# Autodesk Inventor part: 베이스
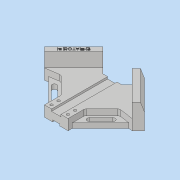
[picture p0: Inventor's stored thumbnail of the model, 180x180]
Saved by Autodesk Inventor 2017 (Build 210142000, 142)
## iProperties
Part Number: 베이스
Material: 일반
Document SubType Name: Modeling
Designer: 00-00
Density: 1 g/cm^3
Appearance: 기본값
Mass: 211.692 g
Surface Area: 407.229 cm^2
Volume: 211.692 cm^3
Author: 00-00
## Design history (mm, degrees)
sketch "스케치1"
  geometry: L1 (0, 84.853)-(84.853, 0); L2 (84.853, 0)-(0, -84.853); L3 (0, -84.853)-(-84.853, 0); L4 (-84.853, 0)-(0, 84.853); L5 (0, 84.853)-(0, -84.853); L6 (84.853, 0)-(-84.853, 0); L7 (0, 84.853)-(120, 84.853); 1 further point
  constraints: 14 end point, 2 midpoint, 2 parallel, 1 equal length, 1 horizontal, 1 perpendicular
  dimensions: "d0" = 120 distance of L1.start L1.end; "d1" = 45 deg angle of L1 L7; "d2" = 120 distance of L1.end L2.end
extrude "돌출1" new body sketch "스케치1" distance "d3" = 42; taper "d4" = 0 deg
sketch "스케치2"
  geometry: L1 (0, 84.853)-(-84.853, 0) reference; L2 (84.853, 0)-(0, 84.853) reference; L3 (-74.246, -10.607)-(0, 63.64); L4 (0, 63.64)-(74.246, -10.607); L5 (-84.853, 0)-(0, -84.853) reference; L6 (0, -84.853)-(84.853, 0) reference; L7 (-74.246, -10.607)-(0, -84.853); L8 (74.246, -10.607)-(0, -84.853); 1 further point
  constraints: 8 end point, 1 collinear, 1 perpendicular, 1 other
  dimensions: "d5" = 15 distance between parallel lines of L1 L3
extrude "돌출2" cut sketch "스케치2" distance "d6" = 24; taper "d7" = 0 deg
sketch "스케치3"
  geometry: L1 (-20, -64.853)-(20, -64.853); L2 (74.246, -10.607)-(0, -84.853) reference; L3 (0, -84.853)-(-74.246, -10.607) reference; 1 further point
  constraints: 2 end point, 2 point on line, 1 horizontal
  dimensions: "d8" = 20 distance from line of L2.end L1
extrude "돌출3" cut sketch "스케치3" stored distance "d9" = 24; taper "d10" = 0 deg
sketch "스케치4"
  geometry: L1 (-35.355, 49.497)-(-16.005, 30.147); L2 (16.005, 30.147)-(35.355, 49.497); L3 (84.853, 0)-(0, 84.853) reference; L4 (0, 84.853)-(-84.853, 0) reference; L5 (-16.005, 30.147)-(16.005, 30.147); L6 (-20, -64.853)-(20, -64.853) reference; 1 further point
  constraints: 6 end point, 2 parallel, 2 point on line, 1 horizontal
  dimensions: "d11" = 50 distance between parallel lines of L2 L4; "d12" = 50 distance between parallel lines of L3 L1; "d13" = 95 distance between parallel lines of L5 L6
extrude "돌출4" cut sketch "스케치4" stored distance "d14" = 24; taper "d15" = 0 deg
sketch "스케치5"
  geometry: L1 (-5, 42)-(0, 27); L2 (-15, 42)-(0, 42) reference; L3 (0, 0)-(0, 42) reference; 1 further point
  constraints: 2 end point, 2 point on line
  dimensions: "d16" = 5 distance from line of L3 L1.start; "d17" = 15 distance from line of L2 L1.end
extrude "돌출5" cut sketch "스케치5" stored distance "d18" = 24; taper "d19" = 0 deg
sketch "스케치6"
  geometry: L1 (-74.246, -10.607)-(-24.749, 38.891) reference; L2 (-74.246, -10.607)-(-49.497, -7.071); L3 (-49.497, -7.071)-(-20, -36.569); L4 (20, -64.853)-(-20, -64.853) reference; L5 (-20, -36.569)-(-20, -64.853); L6 (-20, -64.853)-(-74.246, -10.607) reference; L7 (-84.853, 0)-(-35.355, 49.497) reference; 1 further point
  constraints: 6 end point
  dimensions: "d20" = 20 distance between parallel lines of L6 L3; "d29" = 30 distance from line of L2.end L7; "d30" = 90 deg angle of L4 L5
extrude "돌출6" cut sketch "스케치6" distance "d21" = 10; taper "d22" = 0 deg
sketch "스케치7"
  geometry: L1 (-68.059, -9.723)-(-20, -57.782); L2 (-20, -64.853)-(-74.246, -10.607) reference; L3 (-74.246, -10.607)-(-49.497, -7.071) reference; L4 (-20, -36.569)-(-20, -64.853) reference; 1 further point
  constraints: 2 end point, 2 point on line, 1 parallel
  dimensions: "d23" = 5 distance between parallel lines of L2 L1
extrude "돌출7" cut sketch "스케치7" stored distance "d24" = 8; taper "d25" = 0 deg
sketch "스케치8"
  geometry: L1 (-49.497, -18.385)-(-29.698, -38.184); L2 (-52.326, -21.213)-(-32.527, -41.012); L3 (-26.87, -35.355)-(-46.669, -15.556); L4 (-68.059, -9.723)-(-20, -57.782) reference; L5 (-84.853, 0)-(-35.355, 49.497) reference; L6 (-81.317, -3.536)-(-74.246, -10.607) reference; A1 r 4 centre (-49.497, -18.385) between (-46.669, -15.556) and (-52.326, -21.213); A2 r 4 centre (-29.698, -38.184) between (-32.527, -41.012) and (-26.87, -35.355); 2 further points
  constraints: 8 end point, 4 point on circle, 4 tangent, 2 centre point, 2 parallel, 1 midpoint
  dimensions: "d27" = 4 radius of A2; "d28" = 38 distance from line of L1.start L5; "d31" = 12 distance from line of L6 point (-39.598, -28.284); "d32" = 28 distance of L2.start L2.end
extrude "돌출8" cut sketch "스케치8" stored distance "d33" = 8; taper "d34" = 0 deg
sketch "스케치9"
  geometry: L1 (-20, 64.853)-(-20, 57.782) reference; L2 (20, 64.853)-(-20, 64.853) reference; 3 further points
  constraints: 1 vertical alignment
  dimensions: "d35" = 6 distance from line of L1 point (-14, 58.853); "d36" = 6 distance from line of L2 point (-14, 58.853); "d37" = 18 distance from line of L2 point (-14, 46.853)
hole "구멍1" sketch "스케치9" at (-14, 46.853), (-14, 58.853) diameter "d38" = 4.5; stored, may be unused: countersink angle "d42" = 90 deg, drill point angle "d44" = 118 deg; dims "d39" = 6, "d40" = 8, "d41" = 10, "d43" = 4
sketch "스케치10"
  geometry: L1 (0, 18)-(40, 18) reference; L2 (40, 0)-(0, 0) reference; L3 (12, 18)-(12, 14.5); L4 (12, 14.5)-(28, 14.5); L5 (36.005, 18)-(36.005, 0) reference; L6 (28, 14.5)-(28, 18); L7 (36.005, 18)-(3.995, 18) reference; L8 (0, 0)-(0, 18) reference; L9 (40, 18)-(40, 0) reference; L10 (3.995, 0)-(36.005, 0) reference; L11 (14, 0)-(14, 3); L12 (14, 3)-(26, 3); L13 (26, 3)-(26, 0); 1 further point
  constraints: 12 end point, 5 perpendicular, 4 point on line, 1 vertical
  dimensions: "d45" = 12 distance between parallel lines of L3 L8; "d47" = 12 distance between parallel lines of L9 L6; "d48" = 3.5 distance between parallel lines of L4 L1; "d49" = 12 distance of L11.end L12.end; "d50" = 14 distance between parallel lines of L8 L11; "d51" = 3 distance between parallel lines of L10 L12
extrude "돌출9" cut sketch "스케치10" stored distance "d52" = 8; taper "d53" = 0 deg
extrude "돌출10" cut sketch "스케치10" stored distance "d54" = 8; taper "d55" = 0 deg
sketch "스케치11"
  geometry: L1 (-74.246, -10.607)-(-24.749, 38.891) reference; L2 (-24.749, 38.891)-(-31.82, 45.962) reference; 2 further points
  constraints: 1 other
  dimensions: "d56" = 5 distance from line of L1 point (-53.033, 17.678); "d57" = 35 distance from line of L2 point (-53.033, 17.678)
feature "엠보싱1" sketch "스케치11" dims "d8" = 20, "d58" = 0.5, "d59" = 0
fillet "모깎기1" dims "d60" = 5
sketch "스케치12"
  geometry: 1 further point
node "솔리드1"
mirror "미러1"
mirror "미러2"
